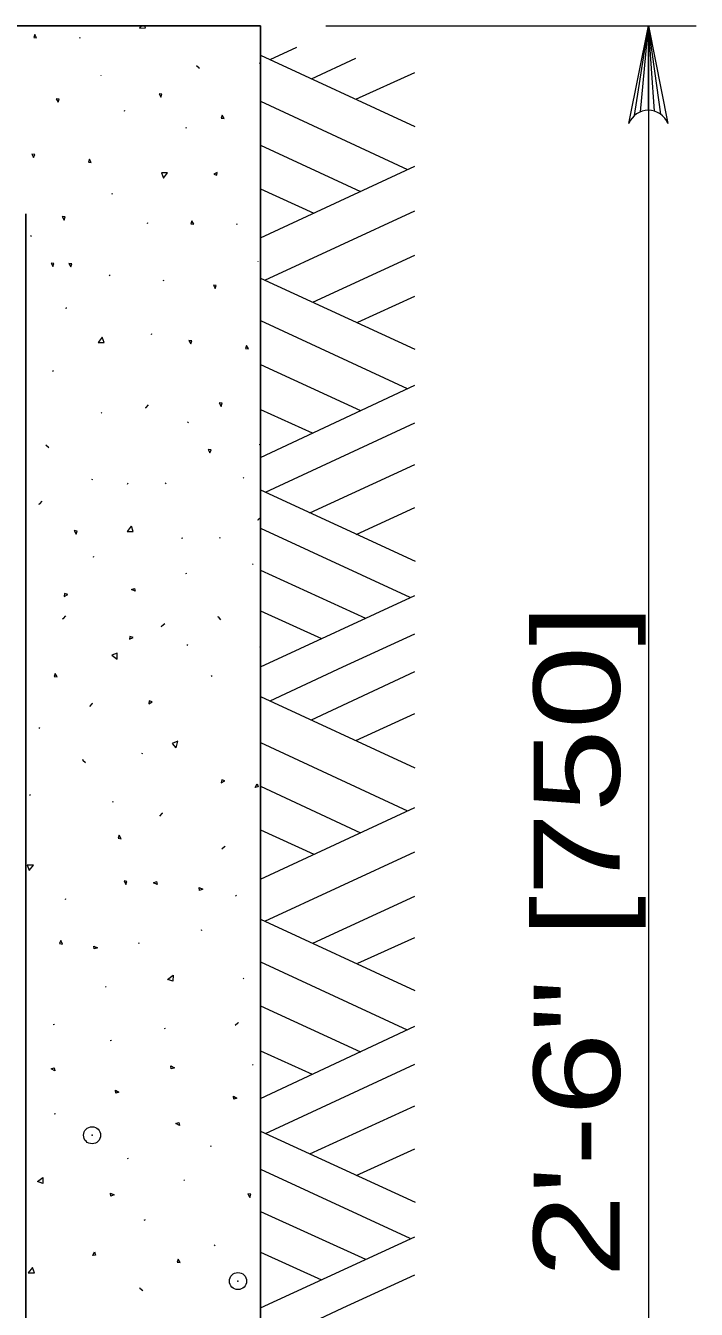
# Model space of a CAD drawing. Extents: x 1083.1 to 1117.1, y 697.4 to 741.4.
# Drawn here: x 1110.624 to 1111.836, y 722.646 to 724.968 of the extents above; entities that cross this region are included whole.
import ezdxf

# ---------------------------------------------------------------- set-up
doc = ezdxf.new("R2010")
doc.units = 0
doc.header["$LTSCALE"] = 0.062
doc.header["$PDMODE"] = 32
doc.header["$PDSIZE"] = 0.031
doc.layers.add('1', color=7, linetype='Continuous', lineweight=13)

msp = doc.modelspace()

# ---------------------------------------------------------------- linework, layer by layer
at = {"layer": '1', "lineweight": 25}
for p, q in [((1110.14883, 724.96767), (1111.04842, 724.96767)), ((1110.62367, 722.1715), (1110.62367, 724.62717))]:
    msp.add_line(p, q, dxfattribs=at)
at = {"layer": '1'}
for p, q in [((1111.16617, 724.96767), (1111.836, 724.96767)), ((1111.7245, 724.8055), (1111.74933, 724.96767)), ((1111.73492, 724.81167), (1111.74933, 724.96767)), ((1111.74933, 724.8145), (1111.74933, 724.96767)), ((1111.76067, 724.81283), (1111.74933, 724.96767)), ((1111.77175, 724.80742), (1111.74933, 724.96767)), ((1110.72158, 724.94617), (1110.72092, 724.94425)), ((1111.06575, 724.90633), (1111.11383, 724.92867)), ((1111.04842, 724.91408), (1111.32692, 724.78517)), ((1111.14008, 724.87175), (1111.22033, 724.90917)), ((1110.76025, 724.87783), (1110.76017, 724.87792)), ((1111.22058, 724.83458), (1111.32692, 724.88292)), ((1111.04842, 724.83108), (1111.31392, 724.70742)), ((1110.80242, 724.81417), (1110.80167, 724.81217)), ((1110.91367, 724.78358), (1110.913, 724.78158)), ((1111.04842, 724.7515), (1111.22917, 724.66767)), ((1111.04842, 724.58375), (1111.32692, 724.71342)), ((1110.77975, 724.66283), (1110.7805, 724.66475)), ((1111.04842, 724.67283), (1111.14442, 724.62875)), ((1111.05625, 724.50767), (1111.32692, 724.63308)), ((1110.84417, 724.611), (1110.84342, 724.609)), ((1111.00558, 724.60917), (1111.00475, 724.60725)), ((1110.63367, 724.58792), (1110.63217, 724.58667)), ((1111.14267, 724.46783), (1111.32692, 724.55258)), ((1111.04417, 724.54083), (1111.04417, 724.54092)), ((1110.77633, 724.51675), (1110.77483, 724.5155)), ((1110.87283, 724.50617), (1110.8735, 724.50817)), ((1111.04842, 724.51117), (1111.32692, 724.38233)), ((1111.22392, 724.43158), (1111.32692, 724.47825)), ((1110.69658, 724.45575), (1110.69742, 724.45775)), ((1111.04842, 724.43417), (1111.313, 724.31133)), ((1110.851, 724.40892), (1110.85183, 724.41075)), ((1110.673, 724.34233), (1110.67383, 724.34433)), ((1111.04842, 724.35458), (1111.22917, 724.27158)), ((1111.04842, 724.18683), (1111.32692, 724.31742)), ((1110.76142, 724.26808), (1110.75983, 724.26683)), ((1111.04842, 724.27333), (1111.14183, 724.231)), ((1110.91758, 724.25092), (1110.916, 724.24967)), ((1111.05717, 724.12375), (1111.32692, 724.24908)), ((1111.04617, 724.21), (1111.04842, 724.21083)), ((1111.04842, 724.20883), (1111.04617, 724.21)), ((1111.1375, 724.08658), (1111.32692, 724.17392)), ((1111.01783, 724.15067), (1111.01667, 724.14917)), ((1110.74258, 724.14758), (1110.74458, 724.14683)), ((1110.80792, 724.13867), (1110.80867, 724.14067)), ((1110.87658, 724.13875), (1110.87733, 724.14075)), ((1111.04842, 724.12808), (1111.32783, 723.99925)), ((1111.22133, 724.04758), (1111.32692, 724.09608)), ((1111.04842, 724.05892), (1111.31825, 723.93433)), ((1110.90558, 724.041), (1110.90758, 724.04167)), ((1110.97417, 724.04117), (1110.97608, 724.042)), ((1110.74625, 724.0065), (1110.74708, 724.0085)), ((1111.03508, 723.99442), (1111.03383, 723.99292)), ((1110.9145, 723.97575), (1110.91383, 723.97767)), ((1111.04842, 723.98275), (1111.23783, 723.89625)), ((1111.04842, 723.80817), (1111.32692, 723.937)), ((1111.04842, 723.90925), (1111.15825, 723.85908)), ((1110.91567, 723.84658), (1110.9165, 723.84858)), ((1111.19717, 723.80817), (1111.32692, 723.86783)), ((1111.04692, 723.84383), (1111.04842, 723.84433)), ((1111.06575, 723.74675), (1111.19717, 723.80817)), ((1110.95908, 723.79258), (1110.95992, 723.79058)), ((1111.14008, 723.71208), (1111.32692, 723.79942)), ((1111.04842, 723.7545), (1111.32692, 723.62567)), ((1111.22058, 723.67492), (1111.32692, 723.72342)), ((1110.6495, 723.69667), (1110.6475, 723.6975)), ((1111.04842, 723.6715), (1111.31392, 723.54792)), ((1110.83275, 723.65217), (1110.83467, 723.65142)), ((1110.63083, 723.57625), (1110.63233, 723.57733)), ((1111.04842, 723.592), (1111.22917, 723.50808)), ((1110.7815, 723.56425), (1110.78067, 723.56242)), ((1111.04842, 723.42417), (1111.32692, 723.55392)), ((1111.04842, 723.51333), (1111.14442, 723.46917)), ((1111.05625, 723.34808), (1111.32692, 723.4735)), ((1110.6955, 723.3885), (1110.69483, 723.38658)), ((1111.00467, 723.39425), (1111.00267, 723.39358)), ((1111.14267, 723.30833), (1111.32692, 723.39308)), ((1111.04842, 723.35158), (1111.32692, 723.22267)), ((1110.94225, 723.33192), (1110.94025, 723.33125)), ((1111.22392, 723.27208), (1111.32692, 723.31875)), ((1110.82883, 723.30842), (1110.82683, 723.30758)), ((1111.04842, 723.27467), (1111.313, 723.15183)), ((1111.01658, 723.24367), (1111.01775, 723.24517)), ((1110.76783, 723.22867), (1110.76908, 723.23017)), ((1111.04842, 723.19508), (1111.22917, 723.112)), ((1110.67358, 723.16092), (1110.67558, 723.16158)), ((1110.87575, 723.15392), (1110.87383, 723.15325)), ((1111.04842, 723.02725), (1111.32692, 723.15792)), ((1110.7785, 723.13225), (1110.7765, 723.13142)), ((1111.04842, 723.11375), (1111.14183, 723.07133)), ((1111.03375, 723.08742), (1111.03492, 723.08892)), ((1111.05717, 722.96425), (1111.32692, 723.08958)), ((1111.1375, 722.92708), (1111.32692, 723.01433)), ((1110.67542, 722.9995), (1110.67733, 723.00033)), ((1111.04842, 722.9685), (1111.32783, 722.83967)), ((1110.95875, 722.94142), (1110.95692, 722.94067)), ((1111.22133, 722.88808), (1111.32692, 722.9365)), ((1110.80742, 722.91875), (1110.80933, 722.91942)), ((1111.04842, 722.89933), (1111.31825, 722.77483)), ((1110.91083, 722.8805), (1110.90958, 722.879)), ((1110.838, 722.80742), (1110.84, 722.80825)), ((1111.04842, 722.82317), (1111.23783, 722.73675)), ((1110.96525, 722.76092), (1110.966, 722.76283)), ((1111.04842, 722.64858), (1111.32692, 722.77742)), ((1111.04842, 722.74975), (1111.15825, 722.69958)), ((1111.19717, 722.64858), (1111.32692, 722.70825)), ((1111.06575, 722.58717), (1111.19717, 722.64858))]:
    msp.add_line(p, q, dxfattribs=at)
at = {"layer": '1', "lineweight": 25}
msp.add_lwpolyline([(1111.04842, 724.96767), (1111.04842, 721.96942), (1110.14883, 721.96942), (1110.14883, 724.368)], dxfattribs=at)
at = {"layer": '1'}
for points in [[(1110.83242, 724.96767), (1110.82925, 724.96333), (1110.84025, 724.9635), (1110.83875, 724.96767)], [(1111.71392, 724.79067), (1111.74933, 724.96767), (1111.78475, 724.79067)], [(1111.74933, 724.96767), (1111.74933, 723.2375), (1111.74933, 721.96942)], [(1110.938, 724.88942), (1110.93742, 724.89083), (1110.93242, 724.895)], [(1111.04842, 724.89917), (1111.04667, 724.899), (1111.04842, 724.90242)], [(1110.87275, 724.69183), (1110.88008, 724.70158), (1110.86925, 724.70142), (1110.87258, 724.692)], [(1110.76208, 724.40442), (1110.75467, 724.39458), (1110.76567, 724.39483), (1110.76217, 724.40417)], [(1110.84025, 724.27658), (1110.84167, 724.27717), (1110.84583, 724.28208)], [(1110.66575, 724.20333), (1110.66508, 724.20467), (1110.66025, 724.20892)], [(1110.64767, 724.10233), (1110.649, 724.103), (1110.65325, 724.108)], [(1110.81458, 724.06267), (1110.80717, 724.05283), (1110.81808, 724.053), (1110.81467, 724.0625)], [(1111.04342, 724.07342), (1111.044, 724.07467), (1111.04842, 724.07842)], [(1110.69042, 723.89475), (1110.69183, 723.89525), (1110.696, 723.90025)], [(1110.97025, 723.89892), (1110.97167, 723.89825), (1110.97583, 723.89325)], [(1110.86933, 723.88067), (1110.86992, 723.88208), (1110.87492, 723.88625)], [(1110.77925, 723.82917), (1110.78908, 723.82175), (1110.78883, 723.83275), (1110.7795, 723.82925)], [(1110.7445, 723.74192), (1110.74308, 723.74142), (1110.73892, 723.73642)], [(1110.89542, 723.66158), (1110.899, 723.67342), (1110.88875, 723.6695), (1110.89525, 723.66183)], [(1110.72642, 723.64092), (1110.727, 723.6395), (1110.732, 723.63533)], [(1110.87083, 723.54367), (1110.8695, 723.54308), (1110.86533, 723.53808)], [(1110.984, 723.48375), (1110.98333, 723.48233), (1110.97833, 723.47817)], [(1110.63, 723.43983), (1110.6375, 723.44967), (1110.6265, 723.44942), (1110.62992, 723.44008)], [(1110.88008, 723.24283), (1110.89, 723.25033), (1110.88983, 723.23933), (1110.88033, 723.24283)], [(1111.00808, 723.16467), (1111.00742, 723.16342), (1111.00258, 723.15925)], [(1110.64483, 722.87725), (1110.65467, 722.88467), (1110.65442, 722.87375), (1110.645, 722.87717)], [(1110.63583, 722.72167), (1110.62833, 722.71183), (1110.63933, 722.712), (1110.63583, 722.7215)], [(1110.82967, 722.68558), (1110.83025, 722.68425), (1110.83525, 722.68008)]]:
    msp.add_lwpolyline(points, dxfattribs=at)
for points in [[(1110.64025, 724.95175), (1110.63825, 724.94617), (1110.6435, 724.94542)], [(1110.68233, 724.82925), (1110.68433, 724.83483), (1110.679, 724.83558)], [(1110.86808, 724.83817), (1110.87008, 724.84375), (1110.86483, 724.84442)], [(1110.97908, 724.80575), (1110.97717, 724.80017), (1110.98233, 724.7995)], [(1110.638, 724.72908), (1110.64, 724.73467), (1110.63475, 724.7355)], [(1110.739, 724.7265), (1110.737, 724.72092), (1110.74225, 724.72025)], [(1110.96367, 724.699), (1110.96925, 724.697), (1110.97, 724.70233)], [(1110.693, 724.61617), (1110.695, 724.62175), (1110.68983, 724.62258)], [(1110.92408, 724.61475), (1110.92208, 724.60917), (1110.92742, 724.60842)], [(1110.67283, 724.532), (1110.67475, 724.53758), (1110.6695, 724.53833)], [(1110.70533, 724.53125), (1110.70717, 724.53683), (1110.70192, 724.5375)], [(1110.96617, 724.49225), (1110.96817, 724.49783), (1110.96292, 724.49858)], [(1110.922, 724.39208), (1110.924, 724.39767), (1110.91867, 724.3985)], [(1111.02283, 724.3895), (1111.02083, 724.38392), (1111.02617, 724.38308)], [(1110.977, 724.27917), (1110.97883, 724.28475), (1110.97367, 724.28558)], [(1110.95667, 724.195), (1110.95867, 724.20058), (1110.95342, 724.20133)], [(1110.715, 724.04808), (1110.71692, 724.05367), (1110.71158, 724.0545)], [(1110.81508, 723.94808), (1110.82067, 723.94992), (1110.82142, 723.94467)], [(1110.69967, 723.93875), (1110.694, 723.94067), (1110.69333, 723.9355)], [(1110.81767, 723.86108), (1110.81208, 723.863), (1110.81125, 723.85783)], [(1110.67725, 723.79617), (1110.67525, 723.79058), (1110.6805, 723.78983)], [(1110.85242, 723.74458), (1110.84683, 723.74658), (1110.84617, 723.74142)], [(1110.98358, 723.60175), (1110.978, 723.60367), (1110.97717, 723.5985)], [(1111.04208, 723.59633), (1111.044, 723.59075), (1111.03875, 723.59008)], [(1110.79283, 723.50342), (1110.791, 723.49792), (1110.79625, 723.49708)], [(1110.80475, 723.4145), (1110.80675, 723.42008), (1110.80158, 723.42075)], [(1110.85475, 723.41767), (1110.86033, 723.41958), (1110.86117, 723.41433)], [(1110.94375, 723.40575), (1110.93817, 723.40375), (1110.93742, 723.40908)], [(1110.68692, 723.313), (1110.68492, 723.3075), (1110.69017, 723.30675)], [(1110.75342, 723.29975), (1110.74775, 723.29783), (1110.74708, 723.30317)], [(1110.66983, 723.08092), (1110.67542, 723.08283), (1110.67608, 723.07758)], [(1110.89242, 723.08308), (1110.88683, 723.08108), (1110.88608, 723.08633)], [(1110.79233, 723.03875), (1110.78675, 723.03692), (1110.78608, 723.04217)], [(1111.0055, 723.02808), (1110.99983, 723.02608), (1110.99908, 723.03142)], [(1110.89508, 722.98225), (1110.90075, 722.98408), (1110.90142, 722.97883)], [(1110.7835, 722.853), (1110.77783, 722.851), (1110.77717, 722.85625)], [(1111.02875, 722.84858), (1111.03067, 722.85417), (1111.02533, 722.85492)], [(1110.74817, 722.74983), (1110.75008, 722.74425), (1110.74492, 722.74358)], [(1110.8995, 722.73692), (1110.8975, 722.73133), (1110.90283, 722.73067)]]:
    msp.add_lwpolyline(points, close=True, dxfattribs=at)
msp.add_arc((1111.74935, 724.77638), 0.0382, 22.08782, 157.91395, dxfattribs=at)
for p in [(1110.74367, 722.96092), (1111.00742, 722.69717)]:
    msp.add_point(p, dxfattribs=at)

# ---------------------------------------------------------------- texts
at = {"layer": '1', "width": 1.3}
msp.add_text('2\'-6" [750]', height=0.156, rotation=90, dxfattribs=at).set_placement((1111.69767, 722.703))

doc.saveas('drawing.dxf')
